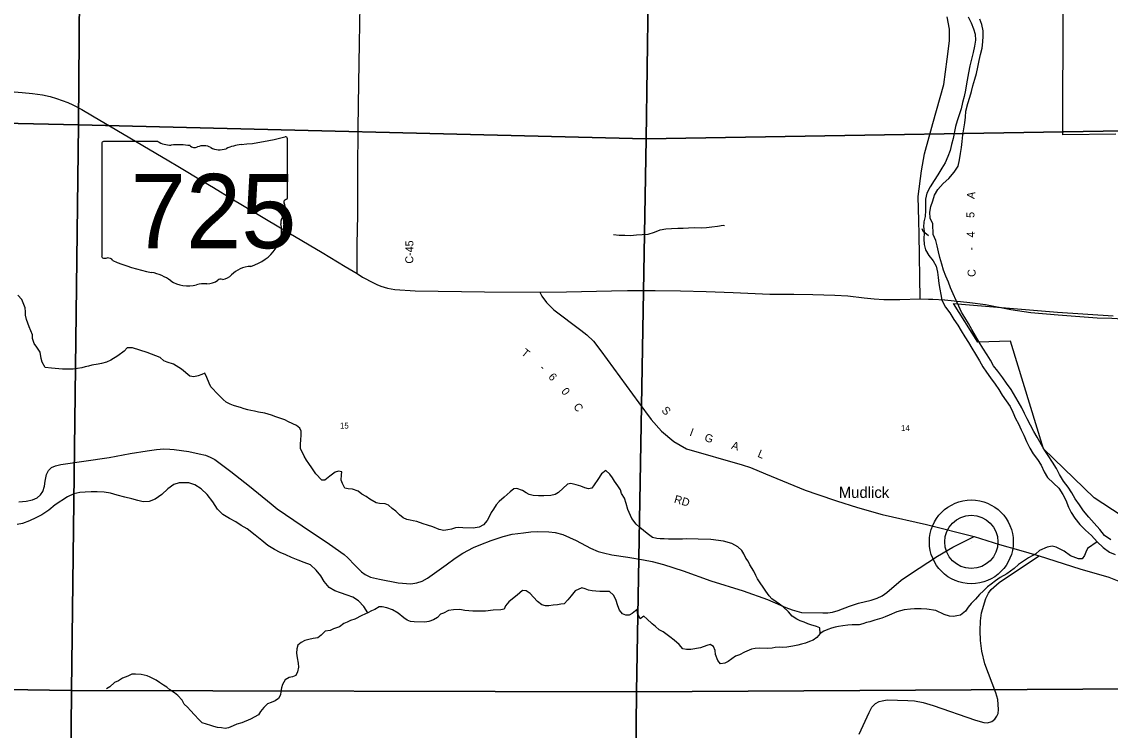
# Model space of a CAD drawing. Extents: x 1312308 to 1684953, y 460642 to 865172.
# Drawn here: x 1426746 to 1436947, y 592735 to 599374 of the extents above; entities that cross this region are included whole.
import ezdxf

# ---------------------------------------------------------------- set-up
doc = ezdxf.new("R2010")
doc.units = 0
for name, color, linetype in [('GM_X_Corporation', 7, 'Continuous'), ('GM_X_County_Road', 7, 'Continuous'), ('GM_X_County_Road_Text', 7, 'Continuous'), ('GM_X_Major_River', 7, 'Continuous'), ('GM_X_Minor_River', 7, 'Continuous'), ('GM_X_Section', 7, 'Continuous'), ('GM_X_Section_Text', 7, 'Continuous'), ('GM_X_State_Location', 7, 'Continuous'), ('GM_X_State_Route', 7, 'Continuous'), ('GM_X_State_Shield', 7, 'Continuous'), ('GM_X_Township_Road', 7, 'Continuous'), ('GM_X_Township_Road_Text', 7, 'Continuous'), ('GM_X_Unincorporated', 7, 'Continuous'), ('GM_X_Unincorporated_Location', 7, 'Continuous'), ('GM_X_Unincorporated_Text', 7, 'Continuous')]:
    doc.layers.add(name, color=color, linetype=linetype)

msp = doc.modelspace()

# ---------------------------------------------------------------- linework, layer by layer
at = {"layer": 'GM_X_Corporation'}
for points in [[(1436998, 598319), (1436502, 598314), (1436509, 600745), (1437159, 600749)], [(1437221, 594636), (1436795, 594913), (1436320, 595371), (1436011, 596380), (1435706, 596370), (1435479, 596733), (1436454, 596654), (1436974, 596618)]]:
    msp.add_lwpolyline(points, dxfattribs=at)
at = {"layer": 'GM_X_County_Road'}
for points in [[(1429890, 597015), (1429890, 597291), (1429897, 597561), (1429895, 597978), (1429900, 598378), (1429904, 598797), (1429912, 599171), (1429919, 599534), (1429926, 599966), (1429931, 600377), (1429935, 600601), (1429950, 600663), (1430007, 600693), (1430239, 600756), (1430608, 600848), (1430862, 600916), (1431186, 601019), (1431364, 601061), (1431589, 601091), (1431814, 601141), (1432015, 601234), (1432197, 601310)], [(1435153, 597507), (1435148, 597735), (1435178, 597977), (1435206, 598137), (1435284, 598419), (1435387, 598785), (1435417, 599023), (1435440, 599196), (1435440, 599304), (1435419, 599419)], [(1435165, 596777), (1435156, 597383), (1435153, 597507)], [(1426718, 594876), (1426788, 594883), (1426848, 594894), (1426892, 594913), (1426923, 594941), (1426944, 594973), (1426959, 595022), (1426966, 595068), (1426978, 595131), (1426997, 595169), (1427026, 595197), (1427061, 595213), (1427112, 595224), (1427564, 595292), (1427763, 595327), (1427920, 595354), (1428010, 595367), (1428079, 595371), (1428134, 595370), (1428173, 595367), (1428313, 595346), (1428410, 595326), (1428468, 595312), (1428513, 595295), (1428554, 595273), (1428706, 595160), (1428881, 595021), (1429083, 594856), (1429141, 594809), (1429373, 594652), (1429629, 594479), (1429766, 594381), (1429801, 594352), (1429869, 594282), (1429883, 594267)], [(1429883, 594267), (1429929, 594221), (1429965, 594195), (1430014, 594171), (1430098, 594151), (1430275, 594115), (1430392, 594107), (1430448, 594115), (1430497, 594132), (1430548, 594159), (1430722, 594284), (1430809, 594348), (1430880, 594394), (1430979, 594446), (1431048, 594476), (1431146, 594513), (1431257, 594552), (1431342, 594571), (1431447, 594586), (1431518, 594593), (1431577, 594597), (1431685, 594595), (1431744, 594587), (1431816, 594570), (1431943, 594512), (1432076, 594441), (1432147, 594411), (1432197, 594396), (1432277, 594380), (1432425, 594358), (1432573, 594333), (1432654, 594316), (1432760, 594288), (1432946, 594228), (1433205, 594134), (1433507, 594042), (1433735, 593961), (1433906, 593884), (1433965, 593862), (1434052, 593840), (1434252, 593834), (1434299, 593835), (1434343, 593842), (1434396, 593857), (1434502, 593897), (1434588, 593926), (1434705, 593954), (1434761, 593972), (1434810, 593995), (1434854, 594025), (1434987, 594141), (1435064, 594196), (1435328, 594365), (1435473, 594451), (1435671, 594550), (1435910, 594475), (1436086, 594426), (1436280, 594368)], [(1434593, 592698), (1434689, 592901), (1434714, 592951), (1434747, 592985), (1434780, 593003), (1434810, 593012), (1434855, 593020), (1435049, 593015), (1435111, 593010), (1435193, 592995), (1435286, 592967), (1435684, 592831), (1435762, 592808), (1435798, 592806), (1435836, 592818), (1435865, 592840), (1435885, 592867), (1435896, 592893), (1435901, 592929), (1435892, 593023), (1435875, 593086), (1435770, 593359), (1435742, 593476), (1435730, 593576), (1435728, 593667), (1435731, 593759), (1435740, 593835), (1435780, 593971), (1435806, 594021), (1435831, 594054), (1435905, 594119), (1436088, 594240), (1436280, 594368)], [(1436280, 594368), (1436663, 594247), (1436934, 594168), (1437027, 594132), (1437302, 593983), (1437522, 593865)]]:
    msp.add_lwpolyline(points, dxfattribs=at)
at = {"layer": 'GM_X_Major_River'}
for points in [[(1435614, 599420), (1435643, 599363), (1435666, 599309), (1435681, 599258), (1435685, 599202), (1435676, 599146), (1435663, 599086), (1435646, 599023), (1435630, 598961), (1435619, 598895), (1435601, 598791), (1435590, 598733), (1435578, 598673), (1435563, 598616), (1435550, 598558), (1435531, 598502), (1435511, 598445), (1435496, 598391), (1435474, 598279), (1435459, 598225), (1435446, 598169), (1435426, 598110), (1435399, 598052), (1435370, 598001), (1435332, 597938), (1435297, 597886), (1435258, 597827), (1435227, 597768), (1435217, 597710), (1435215, 597605), (1435212, 597549), (1435199, 597498), (1435196, 597448), (1435200, 597444)], [(1435283, 597480), (1435260, 597532), (1435255, 597589), (1435264, 597642), (1435283, 597696), (1435301, 597750), (1435332, 597803), (1435381, 597858), (1435434, 597905), (1435483, 597964), (1435521, 598020), (1435534, 598081), (1435543, 598139), (1435552, 598195), (1435558, 598253), (1435565, 598315), (1435576, 598371), (1435585, 598427), (1435590, 598479), (1435595, 598537), (1435613, 598609), (1435632, 598668), (1435647, 598720), (1435658, 598772), (1435678, 598836), (1435693, 598889), (1435706, 598947), (1435718, 599011), (1435731, 599067), (1435746, 599125), (1435753, 599187), (1435756, 599239), (1435755, 599289), (1435743, 599347), (1435726, 599398)], [(1435200, 597444), (1435202, 597396), (1435201, 597340), (1435202, 597288), (1435217, 597237), (1435246, 597184), (1435287, 597133), (1435314, 597083), (1435328, 597028), (1435333, 596978), (1435340, 596921), (1435349, 596869), (1435360, 596817), (1435369, 596764), (1435403, 596701), (1435442, 596646), (1435481, 596585), (1435518, 596530), (1435551, 596479), (1435583, 596420), (1435620, 596367), (1435649, 596314), (1435684, 596259), (1435721, 596198), (1435753, 596141), (1435786, 596089), (1435825, 596036), (1435868, 595978), (1435903, 595927), (1435934, 595875), (1435973, 595821), (1436008, 595769), (1436035, 595716), (1436059, 595657), (1436088, 595606), (1436113, 595551), (1436138, 595501), (1436163, 595440), (1436193, 595379), (1436226, 595324), (1436265, 595271), (1436298, 595218), (1436327, 595155), (1436358, 595104), (1436414, 595049), (1436465, 595002), (1436504, 594945), (1436531, 594890), (1436556, 594827), (1436581, 594774), (1436616, 594721), (1436662, 594664), (1436715, 594611), (1436770, 594559), (1436825, 594500), (1436882, 594446), (1436941, 594405), (1436993, 594382)], [(1436952, 594519), (1436894, 594560), (1436848, 594616), (1436795, 594675), (1436746, 594732), (1436697, 594792), (1436658, 594847), (1436618, 594904), (1436587, 594959), (1436552, 595012), (1436509, 595069), (1436472, 595132), (1436444, 595187), (1436405, 595248), (1436364, 595311), (1436327, 595366), (1436262, 595480), (1436231, 595535), (1436169, 595652), (1436144, 595703), (1436118, 595756), (1436085, 595815), (1436019, 595929), (1435976, 595986), (1435939, 596037), (1435893, 596100), (1435854, 596151), (1435825, 596202), (1435792, 596253), (1435753, 596316), (1435719, 596373), (1435684, 596432), (1435651, 596491), (1435618, 596546), (1435585, 596603), (1435554, 596654), (1435528, 596708), (1435503, 596761), (1435474, 596824), (1435451, 596881), (1435430, 596933), (1435406, 596990), (1435385, 597047), (1435370, 597103), (1435349, 597164), (1435337, 597219), (1435326, 597273), (1435311, 597323), (1435286, 597380), (1435283, 597480)]]:
    msp.add_lwpolyline(points, dxfattribs=at)
at = {"layer": 'GM_X_Minor_River'}
for points in [[(1432292, 597380), (1432344, 597374), (1432398, 597373), (1432452, 597370), (1432507, 597377), (1432561, 597380), (1432617, 597382), (1432676, 597403), (1432730, 597424), (1432781, 597435), (1432835, 597438), (1432893, 597440), (1432945, 597441), (1432995, 597442), (1433053, 597445), (1433113, 597443), (1433164, 597446), (1433214, 597451), (1433266, 597458), (1433320, 597467), (1433332, 597466)], [(1435245, 597367), (1435194, 597407), (1435183, 597433)], [(1430287, 594755), (1430252, 594788), (1430218, 594813), (1430183, 594844), (1430152, 594857), (1430098, 594861), (1430066, 594867), (1430008, 594899), (1429975, 594924), (1429934, 594947), (1429900, 594976), (1429847, 594993), (1429805, 594998), (1429775, 595005), (1429752, 595048), (1429739, 595078), (1429743, 595128), (1429745, 595158), (1429715, 595163), (1429683, 595154), (1429634, 595117), (1429587, 595078), (1429557, 595077), (1429502, 595139), (1429466, 595194), (1429437, 595235), (1429416, 595267), (1429393, 595304), (1429376, 595338), (1429357, 595371), (1429358, 595409), (1429363, 595463), (1429366, 595493), (1429365, 595537), (1429352, 595567), (1429321, 595590), (1429246, 595624), (1429212, 595643), (1429127, 595671), (1429087, 595688), (1429024, 595706), (1428964, 595716), (1428928, 595725), (1428894, 595732), (1428864, 595738), (1428830, 595747), (1428797, 595758), (1428761, 595769), (1428729, 595778), (1428699, 595791), (1428662, 595810), (1428633, 595835), (1428590, 595878), (1428518, 595954), (1428503, 595986), (1428480, 596039), (1428463, 596082), (1428433, 596070), (1428398, 596057), (1428358, 596046), (1428322, 596053), (1428244, 596119), (1428167, 596164), (1428110, 596185), (1428076, 596198), (1428043, 596229), (1427920, 596276), (1427783, 596320), (1427733, 596317), (1427706, 596288), (1427647, 596245), (1427581, 596203), (1427541, 596184), (1427492, 596171), (1427462, 596166), (1427404, 596156), (1427372, 596147), (1427341, 596141), (1427309, 596130), (1427229, 596120), (1427128, 596117), (1427025, 596128), (1426967, 596133), (1426936, 596184), (1426929, 596217), (1426919, 596277), (1426888, 596324), (1426863, 596360), (1426848, 596405), (1426847, 596439), (1426815, 596516), (1426791, 596583), (1426780, 596623), (1426781, 596657), (1426778, 596693), (1426748, 596772), (1426709, 596813)], [(1434229, 593641), (1434225, 593696), (1434195, 593706), (1434141, 593724), (1434112, 593733), (1434078, 593747), (1434042, 593760), (1434011, 593775), (1433967, 593804), (1433931, 593846), (1433882, 593893), (1433848, 593918), (1433817, 593939), (1433774, 593966), (1433751, 593996), (1433718, 594039), (1433641, 594154), (1433624, 594184), (1433607, 594225), (1433568, 594286), (1433555, 594318), (1433532, 594349), (1433513, 594389), (1433494, 594420), (1433457, 594453), (1433402, 594486), (1433322, 594506), (1433204, 594522), (1433086, 594527), (1432980, 594530), (1432938, 594527), (1432870, 594527), (1432808, 594526), (1432766, 594529), (1432730, 594530), (1432698, 594533), (1432658, 594540), (1432607, 594578), (1432572, 594607), (1432539, 594635), (1432505, 594666), (1432463, 594720), (1432438, 594774), (1432427, 594805), (1432409, 594861), (1432394, 594910), (1432367, 594954), (1432356, 594989), (1432331, 595025), (1432300, 595068), (1432281, 595101), (1432258, 595136), (1432219, 595169), (1432180, 595138), (1432145, 595086), (1432111, 595035), (1432090, 595004), (1432058, 594997), (1432022, 595008), (1431987, 595021), (1431943, 595036), (1431893, 595047), (1431859, 595040), (1431777, 594962), (1431746, 594945), (1431704, 594936), (1431640, 594932), (1431588, 594933), (1431540, 594936), (1431502, 594945), (1431472, 594960), (1431439, 594983), (1431387, 595000), (1431357, 594997), (1431324, 594968), (1431267, 594920), (1431220, 594879), (1431191, 594848), (1431166, 594808), (1431145, 594775), (1431128, 594741), (1431107, 594702), (1431073, 594660), (1431033, 594637), (1430978, 594629), (1430880, 594631), (1430842, 594634), (1430812, 594631), (1430772, 594620), (1430740, 594613), (1430701, 594606), (1430659, 594615), (1430598, 594641), (1430547, 594658), (1430509, 594669), (1430449, 594691), (1430415, 594696), (1430386, 594703), (1430354, 594710), (1430322, 594724), (1430287, 594755)], [(1429989, 593834), (1429953, 593894), (1429902, 593948), (1429848, 593981), (1429795, 594000), (1429733, 594022), (1429679, 594043), (1429628, 594072), (1429579, 594130), (1429548, 594181), (1429505, 594236), (1429452, 594285), (1429393, 594308), (1429337, 594330), (1429273, 594353), (1429222, 594379), (1429168, 594402), (1429115, 594429), (1429052, 594467), (1428996, 594512), (1428935, 594564), (1428859, 594622), (1428803, 594655), (1428752, 594688), (1428692, 594720), (1428629, 594757), (1428582, 594808), (1428538, 594874), (1428485, 594943), (1428426, 594997), (1428369, 595034), (1428313, 595053), (1428221, 595053), (1428171, 595038), (1428114, 594996), (1428058, 594943), (1427995, 594900), (1427939, 594879), (1427884, 594876), (1427833, 594888), (1427779, 594903), (1427711, 594920), (1427641, 594938), (1427578, 594958), (1427518, 594967), (1427452, 594970), (1427398, 594968), (1427341, 594967), (1427289, 594964), (1427235, 594949), (1427176, 594921), (1427060, 594847), (1426999, 594798), (1426934, 594755), (1426879, 594725), (1426818, 594698), (1426754, 594673), (1426703, 594662)], [(1436825, 594500), (1436735, 594438), (1436718, 594404), (1436707, 594372), (1436684, 594341), (1436650, 594342), (1436575, 594370), (1436514, 594414), (1436471, 594435), (1436441, 594450), (1436401, 594461), (1436357, 594450), (1436284, 594420), (1436249, 594389), (1436182, 594350), (1436088, 594289), (1436045, 594250), (1435979, 594200), (1435916, 594167), (1435871, 594136), (1435830, 594105), (1435796, 594078), (1435759, 594041), (1435722, 594008), (1435684, 593963), (1435643, 593924), (1435614, 593887), (1435589, 593851), (1435542, 593815), (1435508, 593806), (1435478, 593802), (1435440, 593805), (1435390, 593819), (1435311, 593857), (1435229, 593869), (1435175, 593874), (1435111, 593874), (1435075, 593871), (1435015, 593863), (1434946, 593845), (1434875, 593812), (1434837, 593799), (1434806, 593784), (1434742, 593768), (1434695, 593751), (1434663, 593744), (1434628, 593731), (1434594, 593722), (1434528, 593723), (1434488, 593721), (1434442, 593712), (1434401, 593707), (1434369, 593700), (1434335, 593693), (1434300, 593679), (1434264, 593662), (1434229, 593641), (1434196, 593604), (1434163, 593579), (1434129, 593568), (1434091, 593551), (1434052, 593542), (1434020, 593533), (1433972, 593524), (1433915, 593515), (1433875, 593511), (1433843, 593513), (1433807, 593510), (1433777, 593503), (1433739, 593502), (1433661, 593504), (1433619, 593501), (1433586, 593494), (1433518, 593468), (1433471, 593443), (1433436, 593428), (1433400, 593403), (1433367, 593380), (1433334, 593365), (1433294, 593358), (1433269, 593388), (1433249, 593445), (1433244, 593481), (1433229, 593520), (1433199, 593539), (1433167, 593529), (1433106, 593507), (1433016, 593493), (1432975, 593492), (1432940, 593497), (1432907, 593540), (1432860, 593578), (1432821, 593611), (1432758, 593656), (1432720, 593677), (1432685, 593708), (1432654, 593731), (1432605, 593779), (1432576, 593803), (1432541, 593778), (1432516, 593833)], [(1432516, 593833), (1432513, 593867), (1432468, 593830), (1432438, 593815), (1432408, 593812), (1432376, 593825), (1432349, 593860), (1432332, 593902), (1432314, 593961), (1432291, 594001), (1432254, 594034), (1432224, 594035), (1432165, 594035), (1432125, 594038), (1432093, 594041), (1432058, 594049), (1432026, 594060), (1431994, 594069), (1431931, 594041), (1431894, 593996), (1431865, 593958), (1431830, 593921), (1431798, 593916), (1431767, 593911), (1431725, 593906), (1431685, 593901), (1431653, 593902), (1431621, 593911), (1431580, 593940), (1431543, 593983), (1431512, 594016), (1431473, 594041), (1431439, 594044), (1431389, 594001), (1431344, 593968), (1431312, 593939), (1431280, 593900), (1431268, 593870), (1431235, 593863), (1431165, 593859), (1431091, 593851), (1430973, 593852), (1430899, 593858), (1430851, 593865), (1430793, 593863), (1430746, 593856), (1430700, 593833), (1430669, 593822), (1430643, 593793), (1430606, 593770), (1430561, 593753), (1430523, 593748), (1430423, 593751), (1430389, 593755), (1430359, 593766), (1430328, 593789), (1430273, 593831), (1430220, 593864), (1430166, 593881), (1430125, 593891), (1430095, 593891), (1430054, 593868), (1430023, 593853), (1429989, 593834), (1429932, 593810), (1429869, 593777), (1429827, 593764), (1429796, 593749), (1429764, 593734), (1429725, 593705), (1429668, 593684), (1429636, 593669), (1429591, 593662), (1429552, 593627), (1429520, 593600), (1429477, 593595), (1429435, 593587), (1429399, 593576), (1429366, 593556), (1429333, 593531), (1429323, 593499), (1429321, 593457), (1429328, 593413), (1429337, 593363), (1429340, 593325), (1429331, 593283), (1429316, 593249), (1429283, 593236), (1429253, 593229), (1429216, 593208), (1429189, 593163), (1429180, 593133), (1429175, 593097), (1429170, 593067), (1429151, 593033), (1429121, 593012), (1429084, 592995), (1429050, 592982), (1429015, 592949), (1428984, 592910), (1428965, 592880)], [(1428965, 592880), (1428890, 592838), (1428809, 592806), (1428762, 592791), (1428726, 592776), (1428685, 592757), (1428653, 592752), (1428617, 592757), (1428581, 592760), (1428547, 592771), (1428517, 592780), (1428476, 592791), (1428436, 592806), (1428405, 592835), (1428364, 592880), (1428329, 592921), (1428298, 592950), (1428267, 592981), (1428248, 593017), (1428209, 593060), (1428176, 593087), (1428134, 593115), (1428105, 593139), (1428075, 593156), (1428038, 593183), (1428005, 593204), (1427949, 593234), (1427920, 593244), (1427864, 593258), (1427812, 593261), (1427778, 593260), (1427741, 593243), (1427689, 593223), (1427654, 593199), (1427615, 593184), (1427572, 593142), (1427540, 593122)]]:
    msp.add_lwpolyline(points, dxfattribs=at)
at = {"layer": 'GM_X_Section'}
for points in [[(1427319, 603698), (1427279, 598407), (1421918, 598528), (1421984, 603859)], [(1432672, 603576), (1432598, 598277), (1427279, 598407), (1427319, 603698)], [(1437908, 603579), (1437812, 598364), (1432598, 598277), (1432672, 603576)], [(1421918, 598528), (1427279, 598407), (1427213, 593108), (1421873, 593189)], [(1427279, 598407), (1432598, 598277), (1432507, 593094), (1427213, 593108)], [(1432598, 598277), (1437812, 598364), (1437735, 593125), (1432507, 593094)], [(1421873, 593189), (1427213, 593108), (1427165, 587821), (1421827, 587888)], [(1427213, 593108), (1432507, 593094), (1432454, 587765), (1427165, 587821)], [(1432507, 593094), (1437735, 593125), (1437695, 587736), (1432454, 587765)]]:
    msp.add_lwpolyline(points, close=True, dxfattribs=at)
at = {"layer": 'GM_X_State_Route'}
for points in [[(1426599, 598725), (1426751, 598711), (1426848, 598701), (1426939, 598688), (1427012, 598673), (1427071, 598656), (1427178, 598616), (1427225, 598594), (1427308, 598551), (1427409, 598493), (1427637, 598359), (1428124, 598071), (1428208, 598020), (1428453, 597874), (1428542, 597820), (1428716, 597715), (1428930, 597588), (1429250, 597397), (1429562, 597211), (1429776, 597079), (1429890, 597015), (1429940, 596982), (1430041, 596926), (1430074, 596912)], [(1430074, 596912), (1430111, 596896), (1430173, 596879), (1430243, 596865), (1430432, 596854), (1431084, 596842), (1431602, 596840), (1431852, 596842), (1432274, 596852), (1432422, 596855), (1432682, 596856), (1432919, 596854), (1433161, 596847), (1433414, 596836), (1433758, 596820), (1433981, 596820), (1434161, 596817), (1434365, 596812), (1434488, 596805), (1434642, 596788), (1434733, 596778), (1434824, 596772), (1434976, 596770), (1435165, 596777), (1435244, 596775), (1435283, 596774), (1435392, 596767)], [(1435392, 596767), (1435397, 596767), (1435630, 596743), (1435779, 596725), (1436016, 596679), (1436203, 596650), (1436458, 596628), (1436824, 596601), (1436961, 596595), (1437402, 596567), (1437572, 596556), (1437763, 596551), (1437809, 596556), (1437853, 596565), (1437864, 596568)]]:
    msp.add_lwpolyline(points, dxfattribs=at)
at = {"layer": 'GM_X_State_Shield'}
for p, q in [((1429235, 597725), (1429235, 598278)), ((1427495, 598234), (1427495, 597177)), ((1428022, 598252), (1427512, 598252)), ((1429235, 597725), (1429235, 597725))]:
    msp.add_line(p, q, dxfattribs=at)
for centre, major_axis, start_param, end_param in [((1428615, 599692), (1845, 0), 4.814394, 5.042369), ((1429216, 598280), (19.4, 0), 6.141152, 7.989035), ((1427515, 598236), (20.2, 0), 1.712693, 3.28349), ((1428143, 598375), (196, 0), 4.042523, 4.731795), ((1428208, 597659), (702, 0), 1.404758, 1.657858), ((1428367, 598241), (56.4, 0), 3.836095, 5.185415), ((1428450, 598119), (117, 0), 0.950623, 2.079405), ((1428602, 598287), (141, 0), 4.081561, 5.145723), ((1428851, 597929), (371, 0), 1.699011, 2.107814), ((1429231, 597685), (30, 0), 1.883978, 3.671073), ((1429040, 597615), (180, 0), 5.934695, 6.695948), ((1429215, 597723), (20.7, 0), 5.05454, 6.418171), ((1429305, 597494), (131, 0), 2.387724, 3.262537), ((1428719, 597424), (462, 0), 5.101752, 6.440018), ((1427515, 597175), (20.3, 0), 3.00124, 4.508301), ((1427518, 597283), (155, 0), 4.665946, 4.897461), ((1427550, 597116), (56, 0), 0.519207, 1.627899), ((1428257, 598065), (1333, 0), 4.195997, 4.488961), ((1428913, 596880), (253, 0), 1.647645, 2.488434), ((1427859, 596702), (417, 0), 0.823519, 1.323587), ((1428310, 597111), (265, 0), 4.026481, 4.996735), ((1428482, 597032), (141, 0), 4.691044, 5.507374), ((1428610, 596929), (39.7, 0), 1.147584, 2.315152), ((1428593, 597075), (149, 0), 4.937069, 5.64225), ((1428463, 596746), (217, 0), 1.495662, 1.94098)]:
    msp.add_ellipse(centre, major_axis=major_axis, ratio=0.8, start_param=start_param, end_param=end_param, dxfattribs=at)
at = {"layer": 'GM_X_Township_Road'}
msp.add_lwpolyline([(1431602, 596840), (1431619, 596803), (1431665, 596744), (1431733, 596673), (1431985, 596483), (1432041, 596439), (1432105, 596380), (1432174, 596290), (1432529, 595803), (1432645, 595648), (1432742, 595538), (1432857, 595441), (1432976, 595371), (1433496, 595222), (1433574, 595198), (1433716, 595137), (1434087, 594984), (1434207, 594944), (1434380, 594885), (1434579, 594823), (1434810, 594756), (1435226, 594662), (1435671, 594550)], dxfattribs=at)
at = {"layer": 'GM_X_Unincorporated'}
for radius in [393, 249]:
    msp.add_circle((1435645, 594500), radius, dxfattribs=at)
at = {"layer": 'GM_X_Unincorporated_Location'}
msp.add_line((1435645, 594500), (1435645, 594500), dxfattribs=at)

# ---------------------------------------------------------------- texts
at = {"layer": 'GM_X_County_Road_Text'}
for s, rotation, p in [('A', 82.8488, (1435674, 597711)), ('5', 89.9922, (1435674, 597536)), ('4', 90.9784, (1435677, 597353)), ('C-45', 89.6551, (1430415, 597107)), ('-', 91.253, (1435680, 597230)), ('C', 91.3193, (1435686, 596984))]:
    msp.add_text(s, height=75, rotation=rotation, dxfattribs=at).set_placement(p)
at = {"layer": 'GM_X_Section_Text'}
for s, p in [('15', (1429728, 595562)), ('14', (1434986, 595539))]:
    msp.add_text(s, height=55.3, rotation=0, dxfattribs=at).set_placement(p)
at = {"layer": 'GM_X_State_Location'}
msp.add_text('725', height=0.25, rotation=0, dxfattribs=at).set_placement((1427993, 597562))
for s in ['s', 'r']:
    msp.add_text(s, height=0.25, dxfattribs=at).set_placement((1428346, 597636))
at = {"layer": 'GM_X_State_Shield'}
msp.add_text('725', height=696.1, dxfattribs=at).set_placement((1427767, 597252))
at = {"layer": 'GM_X_Township_Road_Text'}
for s, rotation, p in [('T', 320.862, (1431421, 596260)), ('-', 316.6257, (1431591, 596122)), ('6', 312.3367, (1431676, 596042)), ('0', 308.5208, (1431797, 595909)), ('C', 306.5534, (1431911, 595767)), ('S', 313.14, (1432736, 595728)), ('I', 339.4772, (1432999, 595498)), ('G', 344.0203, (1433139, 595446)), ('A', 343.0005, (1433391, 595374)), ('L', 337.4843, (1433636, 595299)), ('RD', 344.0547, (1432854, 594869))]:
    msp.add_text(s, height=75, rotation=rotation, dxfattribs=at).set_placement(p)
at = {"layer": 'GM_X_Unincorporated_Text'}
msp.add_text('Mudlick', height=104.3, rotation=0, dxfattribs=at).set_placement((1434403, 594912))

doc.saveas('drawing.dxf')
